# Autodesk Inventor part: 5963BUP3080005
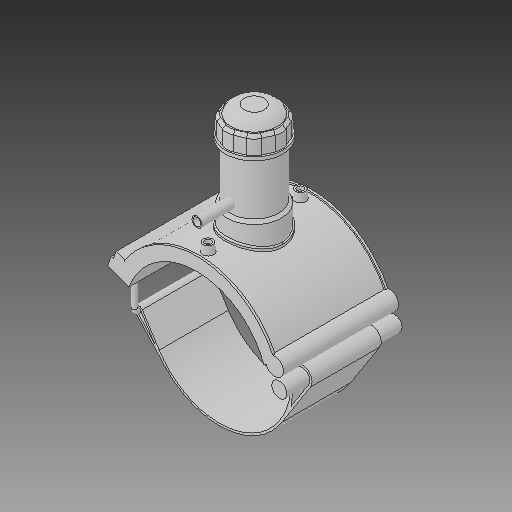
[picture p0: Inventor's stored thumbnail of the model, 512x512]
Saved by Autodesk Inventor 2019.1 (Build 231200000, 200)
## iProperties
Created: 2017-07
Part Number: 5963BUP3080005
Material: Generic
Description: PLASSON TAPPING SADDLE 8''IPS x 1/2''CTS
Document SubType Name: Modeling
Designer: KIM
Density: 1 g/cm^3
Appearance: Default
Author: KIM
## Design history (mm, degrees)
derived "5963BBP_5963BUP.ipt"
feature "Solid1::5963BBP_5963BUP.ipt"
feature "Solid2::5963BBP_5963BUP.ipt"
feature "Solid3::5963BBP_5963BUP.ipt"
tag "TaggingFeature1"
body "Solid1"
body "Solid2"
body "Solid3"
other parameters: "d0" = 218.7, "d2" = 269.748, "d3" = 54.675, "d4" = 176.022, "d5" = 0, "d6" = 0.1, "d8" = 0, "d19" = 6, "d20" = 6, "d21" = 105.6132, "d23" = 0, "d24" = 52.8066, "d26" = 0, "d27" = 3, "d28" = 3, "d29" = 3, "d30" = 72.9, "d31" = 6, "d32" = 0, "d33" = 0, "d34" = 0.6, "d40" = 131.91984, "d41" = 87.48, "d43" = 0, "d45" = 0, "d47" = 232.4592, "d70" = 15, "d72" = 0, "d73" = 6, "d75" = 5, "d76" = 0, "d77" = 10.935, "d78" = 139.35, "d79" = 15, "d80" = 70.4088, "d82" = 5 deg, "d84" = 4, "d85" = 14, "d86" = 0, "d87" = 3, "d88" = 0, "d89" = 1, "d90" = 1, "d91" = 140.8176, "d92" = 0, "d93" = 0.5, "d94" = 115.10526, "d96" = 258.76584, "d97" = 3.52044, "d98" = 0, "d102" = 2.187, "d120" = 140 deg, "d121" = 24.228, "d122" = 20 deg, "d123" = 507.384, "d124" = 152.2152, "d126" = 0, "d143" = 225.261, "d145" = 26.91692, "d149" = 3.2805, "d150" = 29.60862, "d153" = 176.022, "d154" = 0, "d156" = 126.846, "d157" = 160 deg, "d159" = 6.9984, "d161" = 3.2805, "d162" = 105.6132, "d163" = 0, "d164" = 109.35, "d167" = 21.87, "d168" = 123.7522, "d170" = 3.2805, "d172" = 0, "d173" = 1, "d175" = 109.35, "d176" = 20 deg, "d177" = 15.309, "d178" = 34.992, "d180" = 0, "d183" = 13.9968, "d184" = 12.2472, "d185" = 57.20715, "d186" = 57.20715, "d187" = 126.846, "d188" = 10.4976, "d189" = 15.309, "d190" = 0, "d191" = 190.269, "d193" = 6.9984, "d194" = 6.16077, "d195" = 90 deg, "d197" = 0, "d199" = 0, "d200" = 17.496, "d202" = 0, "d203" = 177.038, "d204" = 83.106, "d205" = 61.236, "d206" = 74.358, "d207" = 132.7785, "d208" = 138.08964, "d209" = 164.64534, "d210" = 75.2328, "d211" = 87.48, "d212" = 69.984, "d213" = 51.4116, "d216" = 0, "d217" = 21.87, "d218" = 21.87, "d219" = 4.374, "d222" = 218.7, "d224" = 0, "d225" = 65.024, "d226" = 15.8, "d227" = 12.64, "d228" = 87.376, "d230" = 4.374, "d_" = 218.7, "B_" = 179.832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
